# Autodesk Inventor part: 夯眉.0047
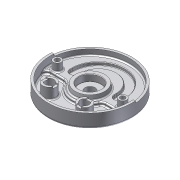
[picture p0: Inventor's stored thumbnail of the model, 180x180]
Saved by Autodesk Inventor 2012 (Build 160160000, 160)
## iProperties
Created: 2015-05
Document SubType Name: Modeling
Density: 2.71 g/cm^3
Material: 알루미늄-6061
Mass: 1082.54 g
Surface Area: 1038.66 cm^2
Volume: 399.463 cm^3
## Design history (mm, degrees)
sketch "스케치1"
  geometry: L1 (-59, -19)-(-59, 19); L2 (59, 19)-(59, -19); L3 (-41, 19)-(-41, -19); L4 (41, -19)-(41, 19); L5 (59, 5)-(41, 5); L6 (-41, 5)-(-59, 5); C1 r 90 at (0, 0); C2 r 95 at (0, 0); A1 r 59 centre (0, 19) between (59, 19) and (-59, 19); A2 r 59 centre (0, -19) between (-59, -19) and (59, -19); A3 r 41 centre (0, -19) between (-41, -19) and (41, -19); A4 r 41 centre (0, 19) between (41, 19) and (-41, 19); 2 further points
  constraints: 12 end point, 8 point on circle, 6 centre point, 5 point on line, 4 tangent, 2 parallel, 1 coincident, 1 collinear, 1 horizontal alignment, 1 midpoint, 1 perpendicular, 1 vertical, 1 vertical alignment, 3 other
  dimensions: "d2" = 180 diameter of C1; "d3" = 156 dimension on A2 A1; "d4" = 118 distance between parallel lines of L2 L1; "d5" = 18 distance between parallel lines of L2 L4; "d8" = 190 diameter of C2; "d117" = 5 distance from line of L5 point (0, 0)
extrude "돌출1" new body sketch "스케치1" distance "d6" = 14; taper "d7" = 0 deg
extrude "돌출2" join sketch "스케치1" distance "d9" = 13; taper "d10" = 0 deg
extrude "돌출3" cut sketch "스케치1" distance "d11" = 7; taper "d12" = 0 deg
sketch "스케치2"
  geometry: C1 r 11.5 at (0, 0); 1 further point
  constraints: 1 centre point, 1 coincident
  dimensions: "d13" = 23 diameter of C1
extrude "돌출4" cut sketch "스케치2" stored distance "d14" = 7; taper "d15" = 0 deg
fillet "모깎기1"
fillet "모깎기2"
sketch "스케치3"
  geometry: L1 (-89.658, 7.844)-(-94.638, 8.28); L2 (89.658, 7.844)-(94.638, 8.28); L3 (0, 0)-(0, -90); A1 r 95 centre (0, 0) between (-94.638, 8.28) and (94.638, 8.28) reference; A2 r 90 centre (0, 0) between (-89.658, 7.844) and (89.658, 7.844) reference; 1 further point
  constraints: 6 end point, 5 point on circle, 1 point on line, 1 vertical, 1 other
  dimensions: "d16" = 190 deg dimension on L2 L1
extrude "돌출5" join sketch "스케치3" distance "d17" = 5; taper "d18" = 0 deg
hole "구멍1" diameter "d21" = 50; stored, may be unused: countersink angle "d25" = 90 deg, drill point angle "d27" = 0 deg; dims "d19" = 10, "d20" = 10, "d22" = 6, "d23" = 4, "d24" = 2, "d26" = 5
fillet "모깎기3" dims "d28" = 0.3
fillet "모깎기5" dims "d42" = 5
sketch "스케치4"
  geometry: C1 r 35 at (0, 0); C2 r 25 at (0, 0); 1 further point
  constraints: 2 centre point, 1 coincident
  dimensions: "d32" = 70 diameter of C1 (derived); "d36" = 10 radial gap between concentric circles of C1 C2
extrude "돌출6" join sketch "스케치4" distance "d33" = 10; taper "d34" = 0 deg
feature "면 기울기2" dims angle "d37" = 10 deg
chamfer "모따기1" distance "d39" = 1; stored, may be unused: second distance "d40" = 2, angle "d41" = 45 deg
sketch "스케치5"
  geometry: L1 (-40.249, -12)-(-89.196, -12); L2 (40.249, -12)-(89.196, -12); A1 r 90 centre (0, 0) between (-89.196, -12) and (89.196, -12) reference; A2 r 42 centre (0, 0) between (-40.249, -12) and (40.249, -12); 1 further point
  constraints: 4 end point, 4 point on circle, 1 centre point, 1 collinear, 1 horizontal, 1 point on line
  dimensions: "d43" = 48 radial gap between concentric circles of A1 A2; "d44" = 12 distance from line of point (0, 0) L1
extrude "돌출7" cut sketch "스케치5" stored distance "d45" = 10; taper "d46" = 0 deg
fillet "모깎기8" dims "d47" = 10
chamfer "모따기2" distance "d49" = 1; stored, may be unused: second distance "d50" = 2, angle "d51" = 45 deg
sketch "스케치7"
  geometry: L1 (36.062, 36.062)-(50.912, 50.912); L2 (-36.062, 36.062)-(-50.912, 50.912); A1 r 72 centre (0, 0) between (50.912, 50.912) and (-50.912, 50.912); A2 r 51 centre (0, 0) between (36.062, 36.062) and (-36.062, 36.062); 1 further point
  constraints: 8 point on circle, 4 end point, 2 centre point, 2 point on line, 1 coincident, 1 horizontal alignment
  dimensions: "d54" = 72 radius of A1; "d55" = 21 radial gap between concentric circles of A1 A2; "d56" = 90 deg angle of L2 L1
extrude "돌출8" join sketch "스케치7" distance "d57" = 5; taper "d58" = 0 deg
fillet "모깎기10" dims "d59" = 5
fillet "모깎기11" dims "d60" = 5
fillet "모깎기12" dims "d61" = 3
sketch "스케치8"
  geometry: C1 r 9 at (74, 0); C2 r 9 at (-74, 0); A1 r 74 centre (0, 0) between (74, 0) and (-74, 0); 1 further point
  constraints: 3 centre point, 2 horizontal alignment, 2 point on circle, 1 coincident, 1 equal radius
  dimensions: "d64" = 18 diameter of C1; "d65" = 148 diameter of A1
extrude "돌출9" join sketch "스케치8" stored distance "d66" = 5; taper "d67" = 0 deg
sketch "스케치11"
  geometry: C1 r 15 at (40, -52); C2 r 15 at (-40, -52); 1 further point
  constraints: 2 centre point, 1 equal radius, 1 horizontal alignment
  dimensions: "d83" = 52 vertical distance of point (0, 0) C1.centre; "d84" = 80 distance of C2.centre C1.centre; "d85" = 40 horizontal distance of point (0, 0) C1.centre (= 0.5 x d84); "d86" = 30 diameter of C1
extrude "돌출10" join sketch "스케치11" stored distance "d87" = 5; taper "d88" = 0 deg
node "구멍3"
node "구멍5"
hole "구멍6" diameter "d93" = 20; stored, may be unused: countersink angle "d97" = 90 deg, drill point angle "d99" = 118 deg; dims "d91" = 10, "d92" = 10, "d94" = 6, "d95" = 4, "d96" = 2, "d98" = 8
hole "구멍7" diameter "d102" = 20; stored, may be unused: countersink angle "d106" = 90 deg, drill point angle "d108" = 118 deg; dims "d100" = 10, "d101" = 10, "d103" = 6, "d104" = 4, "d105" = 2, "d107" = 8
sketch "스케치13"
  geometry: L1 (6, -13.748)-(6, -8); L2 (6, 8)-(6, 13.748); L3 (-6, -13.748)-(-6, -8); L4 (-6, 8)-(-6, 13.748); L5 (-66.252, -6)-(-72, -6); L6 (-88, -6)-(-93.748, -6); L7 (-66.252, 6)-(-72, 6); L8 (-88, 6)-(-93.748, 6); A1 r 15 centre (0, 0) between (6, -13.748) and (6, 13.748) reference; A2 r 10 centre (0, 0) between (6, -8) and (6, 8) reference; A3 r 15 centre (-80, 0) between (-66.252, -6) and (-93.748, -6) reference; A4 r 10 centre (-80, 0) between (-72, -6) and (-88, -6) reference; 1 further point
  constraints: 16 end point, 16 point on circle, 4 equal length, 3 collinear, 2 point on line, 1 perpendicular, 1 vertical
  dimensions: "d109" = 12 distance between parallel lines of L3 L1; "d110" = 6 distance from line of A1.centre L1 (= 0.5 x d109); "d111" = 12 distance between parallel lines of L7 L5; "d112" = 6 distance from line of A3.centre L5 (= 0.5 x d111)
extrude "돌출12" cut sketch "스케치13" distance "d113" = 3; taper "d114" = 0 deg
fillet "모깎기13" dims "d115" = 3
fillet "모깎기14" dims "d116" = 1
sketch "스케치14"
  geometry: C1 r 25 at (0, 0); C2 r 11.5 at (0, 0) reference; 1 further point
  constraints: 1 centre point, 1 coincident
  dimensions: "d120" = 50 diameter of C1
extrude "돌출13" join sketch "스케치14" distance "d121" = 12; taper "d122" = 0 deg
feature "면 기울기3" dims angle "d123" = 15 deg
fillet "모깎기15" dims "d124" = 3
chamfer "모따기3" distance "d125" = 1; stored, may be unused: second distance "d126" = 2, angle "d127" = 45 deg
sketch "스케치6"
  geometry: C1 r 68 at (0, 0); 1 further point
  constraints: 1 centre point, 1 other
  dimensions: "d119" = 136 diameter of C1
feature "엠보싱1" sketch "스케치6" dims "d62" = 0.5, "d63" = 0
node "솔리드1"
fillet "모깎기4" dims "d30" = 3
sketch "스케치9"
  geometry: 1 further point
hole "구멍2" sketch "스케치9" diameter "d68" = 11; stored, may be unused: countersink angle "d72" = 90 deg, drill point angle "d74" = 0 deg; dims "d69" = 6, "d70" = 18, "d71" = 11, "d73" = 8
sketch "스케치10"
  geometry: 1 further point
hole "구멍4" sketch "스케치10" diameter "d75" = 11; stored, may be unused: countersink angle "d79" = 90 deg, drill point angle "d81" = 0 deg; dims "d76" = 6, "d77" = 18, "d78" = 11, "d80" = 8
